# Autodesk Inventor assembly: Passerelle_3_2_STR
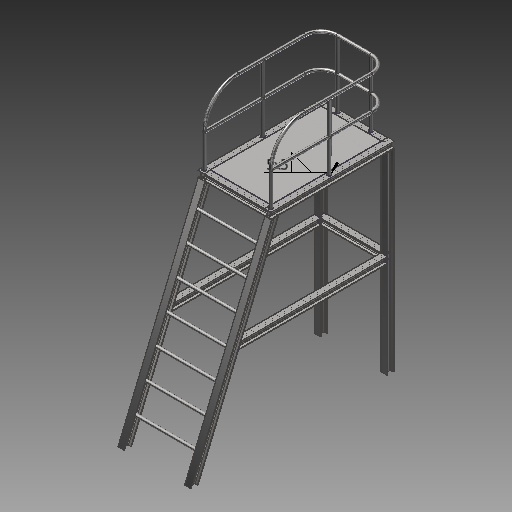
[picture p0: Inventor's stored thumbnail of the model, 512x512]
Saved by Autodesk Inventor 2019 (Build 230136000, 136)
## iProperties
Created: 2018-07
Part Number: Passerelle_3_2_STR
Material: Générique
Document SubType Name: Construction soudée
Designer: Fabian Perrée
Weld Material: Aluminium 6061, soudé
Mass: 574659 g
Surface Area: 487463 cm^2
Volume: 7.20489e+06 cm^3
Density: 0.0797595 g/cm^3
_SolveAssemblyDoc: Frame Generator Solve Assembly
_Version: 15.0.0
Author: Fabian Perrée
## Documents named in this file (4)
- C:\Users\Fabian\Google Drive\04_CAO\01_Inventor\01_Fichiers_exercice_Inventor\02_A_traiter\Frame Generator\Passerelle_3_2_STR.iam
- C:\Users\Fabian\Google Drive\04_CAO\01_Inventor\01_Fichiers_exercice_Inventor\02_A_traiter\Frame Generator\Passerelle_2_3_Sque_STR.ipt
- C:\Users\Fabian\Google Drive\04_CAO\01_Inventor\01_Fichiers_exercice_Inventor\02_A_traiter\Frame Generator\Frame\Frame0001.iam
- C:\Users\Fabian\Google Drive\04_CAO\01_Inventor\01_Fichiers_exercice_Inventor\02_A_traiter\Frame Generator\Frame\Plateforme_3_2_STR.ipt
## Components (3 placed, 3 different names)
1. Passerelle_2_3_Sque_STR:1 — Affleurement:1, Affleurement:2
2. Frame0001:1 [sub-assembly]
3. Plateforme_3_2_STR:1 — Affleurement:1, Affleurement:2
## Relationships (2: Flush 2)
- Affleurement:1 [Flush]: Passerelle_2_3_Sque_STR:1 ↔ Plateforme_3_2_STR:1
- Affleurement:2 [Flush]: Passerelle_2_3_Sque_STR:1 ↔ Plateforme_3_2_STR:1
